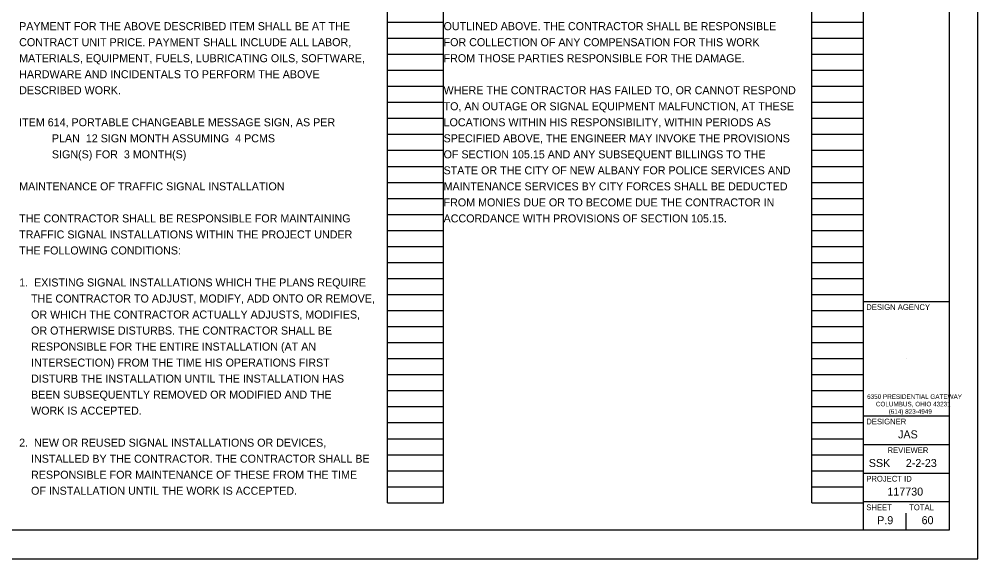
# Model space of a CAD drawing. Extents: x 0 to 34, y 0 to 22.
# Drawn here: x 17.24 to 34, y 0 to 9.43 of the extents above; entities that cross this region are included whole.
import ezdxf

# ---------------------------------------------------------------- set-up
doc = ezdxf.new("R2010")
doc.units = 0
for name, color, linetype in [('SC_Scratch1', 7, 'Continuous'), ('SH_Border', 7, 'Continuous'), ('SH_Cut_Line', 7, 'Continuous'), ('SH_Data', 7, 'Continuous'), ('SH_Text', 7, 'Continuous')]:
    doc.layers.add(name, color=color, linetype=linetype)

msp = doc.modelspace()

# ---------------------------------------------------------------- linework, layer by layer
at = {"layer": 'SC_Scratch1'}
for p, q in [((23.68, 0.98), (23.68, 21.14)), ((24.66, 0.98), (24.66, 21.14)), ((31.1, 0.98), (31.1, 21.14)), ((32, 0.98), (32, 21.14)), ((23.68, 9.38), (24.66, 9.38)), ((31.1, 9.38), (32, 9.38)), ((23.68, 9.1), (24.66, 9.1)), ((31.1, 9.1), (32, 9.1)), ((23.68, 8.82), (24.66, 8.82)), ((31.1, 8.82), (32, 8.82)), ((23.68, 8.54), (24.66, 8.54)), ((31.1, 8.54), (32, 8.54)), ((23.68, 8.26), (24.66, 8.26)), ((31.1, 8.26), (32, 8.26)), ((23.68, 7.98), (24.66, 7.98)), ((31.1, 7.98), (32, 7.98)), ((23.68, 7.7), (24.66, 7.7)), ((31.1, 7.7), (32, 7.7)), ((23.68, 7.42), (24.66, 7.42)), ((31.1, 7.42), (32, 7.42)), ((23.68, 7.14), (24.66, 7.14)), ((31.1, 7.14), (32, 7.14)), ((23.68, 6.86), (24.66, 6.86)), ((31.1, 6.86), (32, 6.86)), ((23.68, 6.58), (24.66, 6.58)), ((31.1, 6.58), (32, 6.58)), ((23.68, 6.3), (24.66, 6.3)), ((31.1, 6.3), (32, 6.3)), ((23.68, 6.02), (24.66, 6.02)), ((31.1, 6.02), (32, 6.02)), ((23.68, 5.74), (24.66, 5.74)), ((31.1, 5.74), (32, 5.74)), ((23.68, 5.46), (24.66, 5.46)), ((31.1, 5.46), (32, 5.46)), ((23.68, 5.18), (24.66, 5.18)), ((31.1, 5.18), (32, 5.18)), ((23.68, 4.9), (24.66, 4.9)), ((31.1, 4.9), (32, 4.9)), ((23.68, 4.62), (24.66, 4.62)), ((31.1, 4.62), (32, 4.62)), ((23.68, 4.34), (24.66, 4.34)), ((31.1, 4.34), (32, 4.34)), ((23.68, 4.06), (24.66, 4.06)), ((31.1, 4.06), (32, 4.06)), ((23.68, 3.78), (24.66, 3.78)), ((31.1, 3.78), (32, 3.78)), ((23.68, 3.5), (24.66, 3.5)), ((31.1, 3.5), (32, 3.5)), ((23.68, 3.22), (24.66, 3.22)), ((31.1, 3.22), (32, 3.22)), ((23.68, 2.94), (24.66, 2.94)), ((31.1, 2.94), (32, 2.94)), ((23.68, 2.66), (24.66, 2.66)), ((31.1, 2.66), (32, 2.66)), ((23.68, 2.38), (24.66, 2.38)), ((31.1, 2.38), (32, 2.38)), ((23.68, 2.1), (24.66, 2.1)), ((31.1, 2.1), (32, 2.1)), ((23.68, 1.82), (24.66, 1.82)), ((31.1, 1.82), (32, 1.82)), ((23.68, 1.54), (24.66, 1.54)), ((31.1, 1.54), (32, 1.54)), ((23.68, 1.26), (24.66, 1.26)), ((31.1, 1.26), (32, 1.26)), ((23.68, 0.98), (24.66, 0.98)), ((31.1, 0.98), (32, 0.98))]:
    msp.add_line(p, q, dxfattribs=at)
at = {"layer": 'SH_Border'}
for p, q in [((32, 0.5), (32, 21.5)), ((32, 4.5), (33.5, 4.5)), ((32, 2.5), (33.5, 2.5)), ((32, 2), (33.5, 2)), ((32, 1.5), (33.5, 1.5)), ((32, 1), (33.5, 1))]:
    msp.add_line(p, q, dxfattribs=at)
msp.add_lwpolyline([(1.5, 21.5), (33.5, 21.5), (33.5, 0.5), (1.5, 0.5)], close=True, dxfattribs=at)
at = {"layer": 'SH_Cut_Line'}
msp.add_lwpolyline([(0, 0), (34, 0), (34, 22), (0, 22)], close=True, dxfattribs=at)
at = {"layer": 'SH_Data'}
for p, q in [((32.75, 3.5), (32.75, 3.5)), ((32.375, 0.675), (32.375, 0.675)), ((32.75, 0.5), (32.75, 0.8))]:
    msp.add_line(p, q, dxfattribs=at)

# ---------------------------------------------------------------- texts
for s, height, p in [('DESIGN AGENCY', 0.1, (32.05, 4.35)), ('6350 PRESIDENTIAL GATEWAY', 0.08, (32.065, 2.795)), ('6350 PRESIDENTIAL GATEWAY', 0.08, (32.065, 2.795)), ('COLUMBUS, OHIO 43231', 0.08, (32.218, 2.665)), ('COLUMBUS, OHIO 43231', 0.08, (32.218, 2.665)), ('(614) 823-4949', 0.08, (32.441, 2.535)), ('(614) 823-4949', 0.08, (32.441, 2.535)), ('DESIGNER', 0.1, (32.05, 2.35)), ('JAS', 0.14, (32.606, 2.105)), ('REVIEWER', 0.1, (32.422, 1.85)), ('SSK', 0.14, (32.094, 1.605)), ('2-2-23', 0.14, (32.741, 1.605)), ('PROJECT ID', 0.1, (32.05, 1.35)), ('117730', 0.14, (32.419, 1.105)), ('SHEET', 0.1, (32.05, 0.85)), ('TOTAL', 0.1, (32.8, 0.85)), ('P.9', 0.14, (32.24, 0.605)), ('60', 0.14, (33.017, 0.605))]:
    msp.add_text(s, height=height, dxfattribs=at).set_placement(p)
at = {"layer": 'SH_Text'}
for s, p in [('PAYMENT FOR THE ABOVE DESCRIBED ITEM SHALL BE AT THE', (17.24, 9.24)), ('OUTLINED ABOVE. THE CONTRACTOR SHALL BE RESPONSIBLE', (24.66, 9.24)), ('CONTRACT UNIT PRICE. PAYMENT SHALL INCLUDE ALL LABOR,', (17.24, 8.96)), ('FOR COLLECTION OF ANY COMPENSATION FOR THIS WORK', (24.66, 8.96)), ('MATERIALS, EQUIPMENT, FUELS, LUBRICATING OILS, SOFTWARE,', (17.24, 8.68)), ('FROM THOSE PARTIES RESPONSIBLE FOR THE DAMAGE.', (24.66, 8.68)), ('HARDWARE AND INCIDENTALS TO PERFORM THE ABOVE', (17.24, 8.4)), ('DESCRIBED WORK.', (17.24, 8.12)), ('WHERE THE CONTRACTOR HAS FAILED TO, OR CANNOT RESPOND', (24.66, 8.12)), ('TO, AN OUTAGE OR SIGNAL EQUIPMENT MALFUNCTION, AT THESE', (24.66, 7.84)), ('ITEM 614, PORTABLE CHANGEABLE MESSAGE SIGN, AS PER', (17.24, 7.56)), ('LOCATIONS WITHIN HIS RESPONSIBILITY, WITHIN PERIODS AS', (24.66, 7.56)), ('           PLAN  12 SIGN MONTH ASSUMING  4 PCMS', (17.24, 7.28)), ('SPECIFIED ABOVE, THE ENGINEER MAY INVOKE THE PROVISIONS', (24.66, 7.28)), ('           SIGN(S) FOR  3 MONTH(S)', (17.24, 7)), ('OF SECTION 105.15 AND ANY SUBSEQUENT BILLINGS TO THE', (24.66, 7)), ('STATE OR THE CITY OF NEW ALBANY FOR POLICE SERVICES AND', (24.66, 6.72)), ('MAINTENANCE OF TRAFFIC SIGNAL INSTALLATION', (17.24, 6.44)), ('MAINTENANCE SERVICES BY CITY FORCES SHALL BE DEDUCTED', (24.66, 6.44)), ('FROM MONIES DUE OR TO BECOME DUE THE CONTRACTOR IN', (24.66, 6.16)), ('THE CONTRACTOR SHALL BE RESPONSIBLE FOR MAINTAINING', (17.24, 5.88)), ('ACCORDANCE WITH PROVISIONS OF SECTION 105.15.', (24.66, 5.88)), ('TRAFFIC SIGNAL INSTALLATIONS WITHIN THE PROJECT UNDER', (17.24, 5.6)), ('THE FOLLOWING CONDITIONS:', (17.24, 5.32)), ('1.  EXISTING SIGNAL INSTALLATIONS WHICH THE PLANS REQUIRE', (17.24, 4.76)), ('    THE CONTRACTOR TO ADJUST, MODIFY, ADD ONTO OR REMOVE,', (17.24, 4.48)), ('    OR WHICH THE CONTRACTOR ACTUALLY ADJUSTS, MODIFIES,', (17.24, 4.2)), ('    OR OTHERWISE DISTURBS. THE CONTRACTOR SHALL BE', (17.24, 3.92)), ('    RESPONSIBLE FOR THE ENTIRE INSTALLATION (AT AN', (17.24, 3.64)), ('    INTERSECTION) FROM THE TIME HIS OPERATIONS FIRST', (17.24, 3.36)), ('    DISTURB THE INSTALLATION UNTIL THE INSTALLATION HAS', (17.24, 3.08)), ('    BEEN SUBSEQUENTLY REMOVED OR MODIFIED AND THE', (17.24, 2.8)), ('    WORK IS ACCEPTED.', (17.24, 2.52)), ('2.  NEW OR REUSED SIGNAL INSTALLATIONS OR DEVICES,', (17.24, 1.96)), ('    INSTALLED BY THE CONTRACTOR. THE CONTRACTOR SHALL BE', (17.24, 1.68)), ('    RESPONSIBLE FOR MAINTENANCE OF THESE FROM THE TIME', (17.24, 1.4)), ('    OF INSTALLATION UNTIL THE WORK IS ACCEPTED.', (17.24, 1.12))]:
    msp.add_text(s, height=0.14, dxfattribs=at).set_placement(p)

doc.saveas('drawing.dxf')
